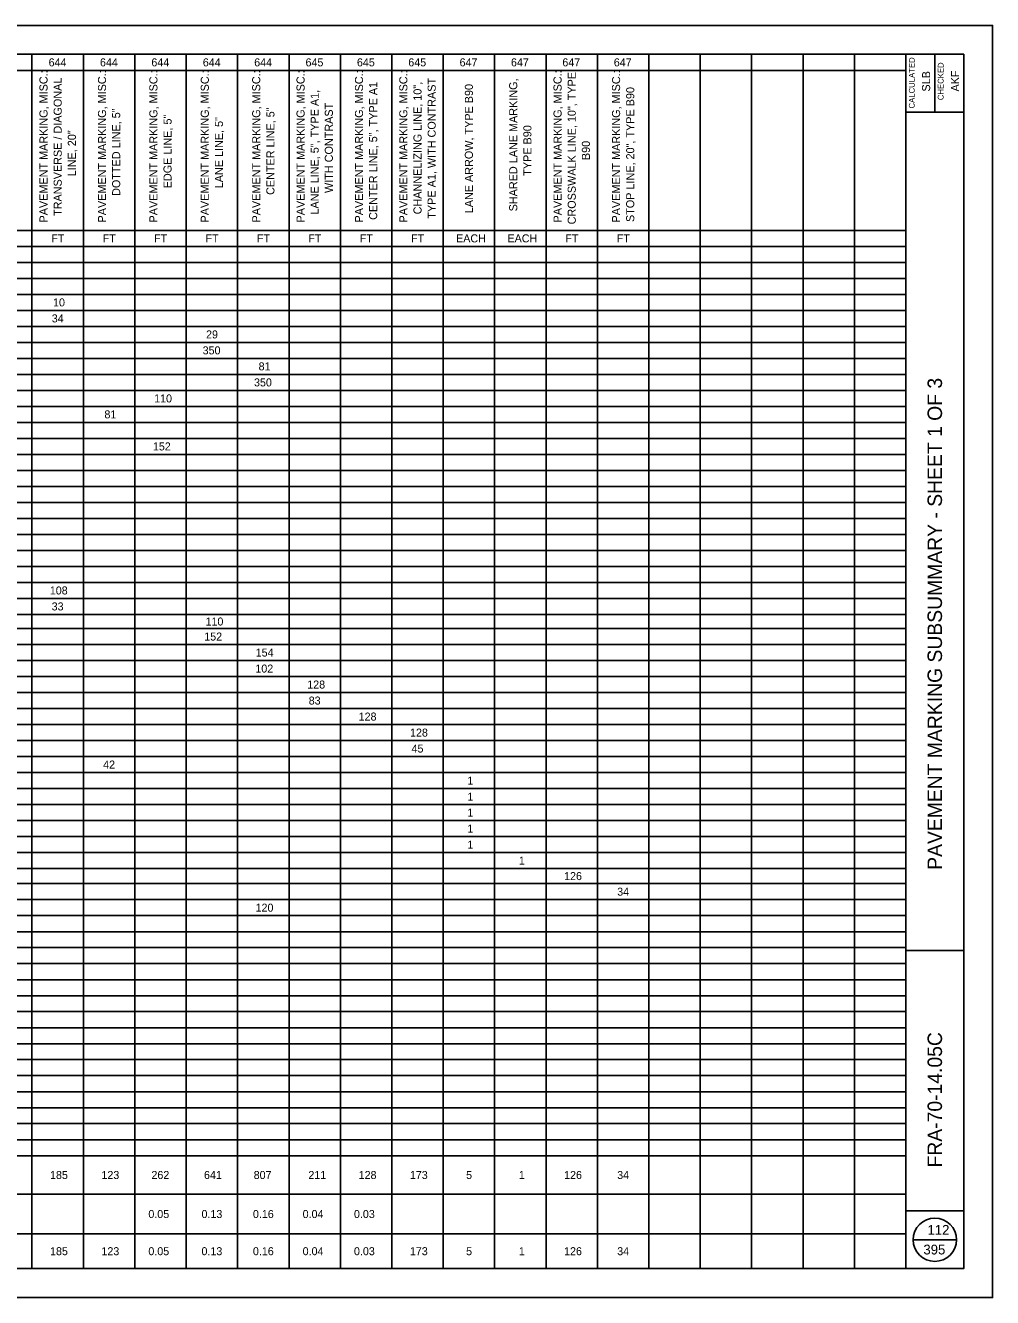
# Model space of a CAD drawing. Extents: x 1822379 to 1824724, y 710341 to 711455.
# Drawn here: x 1822396.38 to 1822413.11, y 711198.87 to 711220.87 of the extents above; entities that cross this region are included whole.
import ezdxf

# ---------------------------------------------------------------- set-up
doc = ezdxf.new("R2010")
doc.units = 0
for name, color, linetype in [('SH_Border', 7, 'Continuous'), ('SH_Cut_Line', 7, 'Continuous'), ('SH_Data', 7, 'Continuous'), ('SH_Text', 7, 'Continuous'), ('TX_P_20', 7, 'Continuous')]:
    doc.layers.add(name, color=color, linetype=linetype)

msp = doc.modelspace()

# ---------------------------------------------------------------- linework, layer by layer
at = {"layer": 'SH_Border'}
for p, q in [((1822411.613, 711199.366), (1822411.613, 711220.366)), ((1822412.113, 711220.366), (1822412.113, 711219.366)), ((1822411.613, 711219.366), (1822412.613, 711219.366)), ((1822411.613, 711204.866), (1822412.613, 711204.866)), ((1822411.613, 711200.366), (1822412.613, 711200.366))]:
    msp.add_line(p, q, dxfattribs=at)
msp.add_lwpolyline([(1822381.113, 711220.366), (1822412.613, 711220.366), (1822412.613, 711199.366), (1822381.113, 711199.366)], close=True, dxfattribs=at)
at = {"layer": 'SH_Cut_Line'}
msp.add_lwpolyline([(1822379.113, 711198.866), (1822413.113, 711198.866), (1822413.113, 711220.866), (1822379.113, 711220.866)], close=True, dxfattribs=at)
at = {"layer": 'SH_Data'}
for p, q in [((1822381.113, 711220.366), (1822411.613, 711220.366)), ((1822396.494, 711220.366), (1822396.494, 711199.366)), ((1822397.384, 711220.366), (1822397.384, 711199.366)), ((1822398.273, 711220.366), (1822398.273, 711199.366)), ((1822399.162, 711220.366), (1822399.162, 711199.366)), ((1822400.052, 711220.366), (1822400.052, 711199.366)), ((1822400.941, 711220.366), (1822400.941, 711199.366)), ((1822401.83, 711220.366), (1822401.83, 711199.366)), ((1822402.719, 711220.366), (1822402.719, 711199.366)), ((1822403.609, 711220.366), (1822403.609, 711199.366)), ((1822404.498, 711220.366), (1822404.498, 711199.366)), ((1822405.387, 711220.366), (1822405.387, 711199.366)), ((1822406.277, 711220.366), (1822406.277, 711199.366)), ((1822407.166, 711220.366), (1822407.166, 711199.366)), ((1822408.055, 711220.366), (1822408.055, 711199.366)), ((1822408.945, 711220.366), (1822408.945, 711199.366)), ((1822409.834, 711220.366), (1822409.834, 711199.366)), ((1822410.723, 711220.366), (1822410.723, 711199.366)), ((1822411.613, 711220.366), (1822411.613, 711199.366)), ((1822390.269, 711220.089), (1822411.613, 711220.089)), ((1822390.269, 711217.321), (1822411.613, 711217.321)), ((1822381.113, 711217.045), (1822411.613, 711217.045)), ((1822381.113, 711216.768), (1822411.613, 711216.768)), ((1822381.113, 711216.491), (1822411.613, 711216.491)), ((1822381.113, 711216.214), (1822411.613, 711216.214)), ((1822381.113, 711215.938), (1822411.613, 711215.938)), ((1822381.113, 711215.661), (1822411.613, 711215.661)), ((1822381.113, 711215.384), (1822411.613, 711215.384)), ((1822381.113, 711215.107), (1822411.613, 711215.107)), ((1822381.113, 711214.831), (1822411.613, 711214.831)), ((1822381.113, 711214.554), (1822411.613, 711214.554)), ((1822381.113, 711214.277), (1822411.613, 711214.277)), ((1822381.113, 711214), (1822411.613, 711214)), ((1822381.113, 711213.724), (1822411.613, 711213.724)), ((1822381.113, 711213.447), (1822411.613, 711213.447)), ((1822381.113, 711213.17), (1822411.613, 711213.17)), ((1822381.113, 711212.893), (1822411.613, 711212.893)), ((1822381.113, 711212.617), (1822411.613, 711212.617)), ((1822381.113, 711212.34), (1822411.613, 711212.34)), ((1822381.113, 711212.063), (1822411.613, 711212.063)), ((1822381.113, 711211.786), (1822411.613, 711211.786)), ((1822381.113, 711211.51), (1822411.613, 711211.51)), ((1822381.113, 711211.233), (1822411.613, 711211.233)), ((1822381.113, 711210.956), (1822411.613, 711210.956)), ((1822381.113, 711210.68), (1822411.613, 711210.68)), ((1822381.113, 711210.435), (1822411.613, 711210.435)), ((1822381.113, 711210.159), (1822411.613, 711210.159)), ((1822381.113, 711209.882), (1822411.613, 711209.882)), ((1822381.113, 711209.605), (1822411.613, 711209.605)), ((1822381.113, 711209.328), (1822411.613, 711209.328)), ((1822381.113, 711209.052), (1822411.613, 711209.052)), ((1822381.113, 711208.775), (1822411.613, 711208.775)), ((1822381.113, 711208.498), (1822411.613, 711208.498)), ((1822381.113, 711208.221), (1822411.613, 711208.221)), ((1822381.113, 711207.945), (1822411.613, 711207.945)), ((1822381.113, 711207.668), (1822411.613, 711207.668)), ((1822381.113, 711207.391), (1822411.613, 711207.391)), ((1822381.113, 711207.114), (1822411.613, 711207.114)), ((1822381.113, 711206.838), (1822411.613, 711206.838)), ((1822381.113, 711206.561), (1822411.613, 711206.561)), ((1822381.113, 711206.284), (1822411.613, 711206.284)), ((1822381.113, 711206.024), (1822411.613, 711206.024)), ((1822381.113, 711205.747), (1822411.613, 711205.747)), ((1822381.113, 711205.47), (1822411.613, 711205.47)), ((1822381.113, 711205.193), (1822411.613, 711205.193)), ((1822381.113, 711204.917), (1822411.613, 711204.917)), ((1822381.113, 711204.64), (1822411.613, 711204.64)), ((1822381.113, 711204.363), (1822411.613, 711204.363)), ((1822381.113, 711204.086), (1822411.613, 711204.086)), ((1822381.113, 711203.81), (1822411.613, 711203.81)), ((1822381.113, 711203.533), (1822411.613, 711203.533)), ((1822381.113, 711203.256), (1822411.613, 711203.256)), ((1822381.113, 711202.98), (1822411.613, 711202.98)), ((1822381.113, 711202.703), (1822411.613, 711202.703)), ((1822381.113, 711202.426), (1822411.613, 711202.426)), ((1822381.113, 711202.149), (1822411.613, 711202.149)), ((1822381.113, 711201.873), (1822411.613, 711201.873)), ((1822381.113, 711201.596), (1822411.613, 711201.596)), ((1822381.113, 711201.319), (1822411.613, 711201.319)), ((1822381.113, 711200.652), (1822411.613, 711200.652)), ((1822381.113, 711199.968), (1822411.613, 711199.968)), ((1822411.738, 711199.866), (1822412.488, 711199.866)), ((1822381.113, 711199.366), (1822411.613, 711199.366))]:
    msp.add_line(p, q, dxfattribs=at)
msp.add_circle((1822412.113, 711199.866), 0.375, dxfattribs=at)

# ---------------------------------------------------------------- texts
for s, height, p in [('CALCULATED', 0.1, (1822411.765, 711219.43)), ('CHECKED', 0.1, (1822412.265, 711219.573)), ('SLB', 0.14, (1822412.033, 711219.722)), ('AKF', 0.14, (1822412.533, 711219.723)), ('PAVEMENT MARKING SUBSUMMARY - SHEET 1 OF 3', 0.25, (1822412.238, 711206.263)), ('FRA-70-14.05C', 0.25, (1822412.238, 711201.115))]:
    msp.add_text(s, height=height, rotation=90, dxfattribs=at).set_placement(p)
at = {"layer": 'SH_Text'}
for s, height, p in [('644', 0.1384, (1822396.782, 711220.158)), ('644', 0.1384, (1822397.671, 711220.158)), ('644', 0.1384, (1822398.56, 711220.158)), ('644', 0.1384, (1822399.45, 711220.158)), ('644', 0.1384, (1822400.339, 711220.158)), ('645', 0.1384, (1822401.227, 711220.158)), ('645', 0.1384, (1822402.116, 711220.158)), ('645', 0.1384, (1822403.005, 711220.158)), ('647', 0.1384, (1822403.892, 711220.158)), ('647', 0.1384, (1822404.781, 711220.158)), ('647', 0.1384, (1822405.67, 711220.158)), ('647', 0.1384, (1822406.56, 711220.158)), ('FT', 0.1384, (1822396.829, 711217.114)), ('FT', 0.1384, (1822397.718, 711217.114)), ('FT', 0.1384, (1822398.607, 711217.114)), ('FT', 0.1384, (1822399.497, 711217.114)), ('FT', 0.1384, (1822400.386, 711217.114)), ('FT', 0.1384, (1822401.275, 711217.114)), ('FT', 0.1384, (1822402.165, 711217.114)), ('FT', 0.1384, (1822403.054, 711217.114)), ('EACH', 0.1384, (1822403.832, 711217.114)), ('EACH', 0.1384, (1822404.721, 711217.114)), ('FT', 0.1384, (1822405.722, 711217.114)), ('FT', 0.1384, (1822406.611, 711217.114)), ('10', 0.1384, (1822396.859, 711216.007)), ('34', 0.1384, (1822396.837, 711215.73)), ('29', 0.1384, (1822399.506, 711215.453)), ('350', 0.1384, (1822399.447, 711215.177)), ('81', 0.1384, (1822400.415, 711214.9)), ('350', 0.1384, (1822400.336, 711214.623)), ('110', 0.1384, (1822398.608, 711214.346)), ('81', 0.1384, (1822397.748, 711214.07)), ('152', 0.1384, (1822398.586, 711213.516)), ('108', 0.1384, (1822396.803, 711211.025)), ('33', 0.1384, (1822396.835, 711210.749)), ('110', 0.1384, (1822399.497, 711210.488)), ('152', 0.1384, (1822399.475, 711210.228)), ('154', 0.1384, (1822400.365, 711209.951)), ('102', 0.1384, (1822400.359, 711209.674)), ('128', 0.1384, (1822401.257, 711209.398)), ('83', 0.1384, (1822401.282, 711209.121)), ('128', 0.1384, (1822402.146, 711208.844)), ('128', 0.1384, (1822403.035, 711208.567)), ('45', 0.1384, (1822403.061, 711208.291)), ('42', 0.1384, (1822397.726, 711208.014)), ('1', 0.138, (1822404.027, 711207.737)), ('1', 0.138, (1822404.027, 711207.46)), ('1', 0.138, (1822404.027, 711207.184)), ('1', 0.138, (1822404.027, 711206.907)), ('1', 0.138, (1822404.027, 711206.63)), ('1', 0.138, (1822404.917, 711206.353)), ('126', 0.1384, (1822405.7, 711206.085)), ('34', 0.1384, (1822406.619, 711205.816)), ('120', 0.1384, (1822400.363, 711205.539)), ('185', 0.1384, (1822396.807, 711200.916)), ('123', 0.1384, (1822397.696, 711200.916)), ('262', 0.1384, (1822398.561, 711200.916)), ('641', 0.1384, (1822399.47, 711200.916)), ('807', 0.1384, (1822400.33, 711200.916)), ('211', 0.1384, (1822401.276, 711200.916)), ('128', 0.1384, (1822402.146, 711200.916)), ('173', 0.1384, (1822403.032, 711200.916)), ('5', 0.138, (1822404.005, 711200.916)), ('1', 0.138, (1822404.917, 711200.916)), ('126', 0.1384, (1822405.7, 711200.916)), ('34', 0.1384, (1822406.619, 711200.916)), ('0.05', 0.1384, (1822398.508, 711200.241)), ('0.13', 0.1384, (1822399.427, 711200.241)), ('0.16', 0.1384, (1822400.317, 711200.241)), ('0.04', 0.1384, (1822401.177, 711200.241)), ('0.03', 0.1384, (1822402.065, 711200.241)), ('185', 0.1384, (1822396.807, 711199.598)), ('123', 0.1384, (1822397.696, 711199.598)), ('0.05', 0.1384, (1822398.508, 711199.598)), ('0.13', 0.1384, (1822399.427, 711199.598)), ('0.16', 0.1384, (1822400.317, 711199.598)), ('0.04', 0.1384, (1822401.177, 711199.598)), ('0.03', 0.1384, (1822402.065, 711199.598)), ('173', 0.1384, (1822403.032, 711199.598)), ('5', 0.138, (1822404.005, 711199.598)), ('1', 0.138, (1822404.917, 711199.598)), ('126', 0.1384, (1822405.7, 711199.598)), ('34', 0.1384, (1822406.619, 711199.598))]:
    msp.add_text(s, height=height, dxfattribs=at).set_placement(p)
for s, height, p in [('PAVEMENT MARKING, MISC.:', 0.13998, (1822396.764, 711217.458)), ('PAVEMENT MARKING, MISC.:', 0.13998, (1822397.776, 711217.458)), ('PAVEMENT MARKING, MISC.:', 0.13998, (1822398.665, 711217.458)), ('PAVEMENT MARKING, MISC.:', 0.13998, (1822399.554, 711217.458)), ('PAVEMENT MARKING, MISC.:', 0.13998, (1822400.444, 711217.458)), ('PAVEMENT MARKING, MISC.:', 0.13998, (1822401.211, 711217.458)), ('PAVEMENT MARKING, MISC.:', 0.13998, (1822402.222, 711217.458)), ('PAVEMENT MARKING, MISC.:', 0.13998, (1822402.989, 711217.458)), ('PAVEMENT MARKING, MISC.:', 0.13998, (1822405.657, 711217.458)), ('CROSSWALK LINE, 10", TYPE', 0.13998, (1822405.902, 711217.425)), ('PAVEMENT MARKING, MISC.:', 0.13998, (1822406.669, 711217.458)), ('TRANSVERSE / DIAGONAL', 0.13998, (1822397.009, 711217.571)), ('CENTER LINE, 5", TYPE A1', 0.13998, (1822402.467, 711217.503)), ('CHANNELIZING LINE, 10",', 0.13998, (1822403.234, 711217.598)), ('TYPE A1, WITH CONTRAST', 0.13998, (1822403.479, 711217.524)), ('LANE ARROW, TYPE B90', 0.13998, (1822404.123, 711217.617)), ('SHARED LANE MARKING,', 0.13998, (1822404.89, 711217.65)), ('STOP LINE, 20", TYPE B90', 0.13998, (1822406.914, 711217.466)), ('LANE LINE, 5", TYPE A1,', 0.13998, (1822401.455, 711217.594)), ('WITH CONTRAST', 0.13998, (1822401.7, 711217.968)), ('DOTTED LINE, 5"', 0.13998, (1822398.021, 711217.918)), ('EDGE LINE, 5"', 0.13998, (1822398.91, 711218.049)), ('CENTER LINE, 5"', 0.13998, (1822400.689, 711217.935)), ('LANE LINE, 5"', 0.13998, (1822399.799, 711218.049)), ('TYPE B90', 0.14, (1822405.135, 711218.266)), ('LINE, 20"', 0.14, (1822397.254, 711218.257)), ('B90', 0.14, (1822406.147, 711218.537))]:
    msp.add_text(s, height=height, rotation=90, dxfattribs=at).set_placement(p)
at = {"layer": 'TX_P_20'}
for s, p in [('112', (1822411.987, 711199.951)), ('395', (1822411.916, 711199.611))]:
    msp.add_text(s, height=0.17, dxfattribs=at).set_placement(p)

doc.saveas('drawing.dxf')
